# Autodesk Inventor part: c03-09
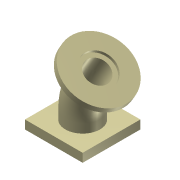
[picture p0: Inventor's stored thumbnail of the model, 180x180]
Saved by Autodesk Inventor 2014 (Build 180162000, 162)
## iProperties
Created: 2011-11
Part Number: c03-09
Material: Iron, Cast
Document SubType Name: Modeling
Designer: Thom Tremblay
Density: 7.25 g/cm^3
Mass: 1087.5 g
Surface Area: 260 cm^2
Volume: 150 cm^3
Appearance: Nylon 6
Author: Thom Tremblay
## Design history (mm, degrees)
sketch "Sketch1"
  geometry: L1 (50, -50)-(-50, -50); L2 (-50, -50)-(-50, 50); L3 (-50, 50)-(50, 50); L4 (50, 50)-(50, -50); C1 r 20 at (0, 0); C2 r 30 at (0, 0); 3 further points
  constraints: 8 end point, 2 centre point, 2 coincident, 2 midpoint, 2 parallel, 2 perpendicular, 1 horizontal, 1 horizontal alignment, 1 vertical alignment
  dimensions: "d0" = 100 distance of L2.end L3.end; "d3" = 40 diameter of C1; "d4" = 10 radial gap between concentric circles of C2 C1
extrude "Extrusion1" new body sketch "Sketch1" distance "d1" = 15; taper "d2" = 0 deg
sketch "Sketch2"
  geometry: L1 (0, 0)-(0, 30); L2 (12.794, 77.746)-(27.794, 103.727); A1 r 95.493 centre (95.493, 30) between (12.794, 77.746) and (0, 30)
  constraints: 4 end point, 2 point on circle, 2 tangent, 1 centre point, 1 vertical
  dimensions: "d5" = 30 distance of L1.start L1.end; "d7" = 50 dimension on A1; "d9" = 30 distance of L2.start L2.end; "d10" = 30 deg angle of L2 L1
sketch "Sketch3"
  geometry: L1 (12.794, 77.746)-(27.794, 103.727) reference; L2 (27.794, 103.727)-(75.425, 76.227); L3 (75.425, 76.227)-(70.425, 67.567); L4 (70.425, 67.567)-(22.794, 95.067); L5 (22.794, 95.067)-(27.794, 103.727); 2 further points
  constraints: 8 end point, 2 parallel, 2 perpendicular
  dimensions: "d11" = 110 diameter of L3 L5; "d13" = 10 distance between parallel lines of L2 L4
revolve "Revolution1" sketch "Sketch3" stored, may be unused: angle "d14" = 90 deg
sweep "Sweep1" dims "d15" = 0
sweep "Sweep2" dims "d16" = 0
sketch "Sketch4"
  geometry: C1 r 55 at (0, 0) reference; C2 r 27.5 at (0, 0); 1 further point
  constraints: 1 centre point, 1 coincident
  dimensions: "d17" = 55 diameter of C2
extrude "Extrusion2" cut sketch "Sketch4" distance "d18" = 5; taper "d19" = 0 deg
body "Solid1"
